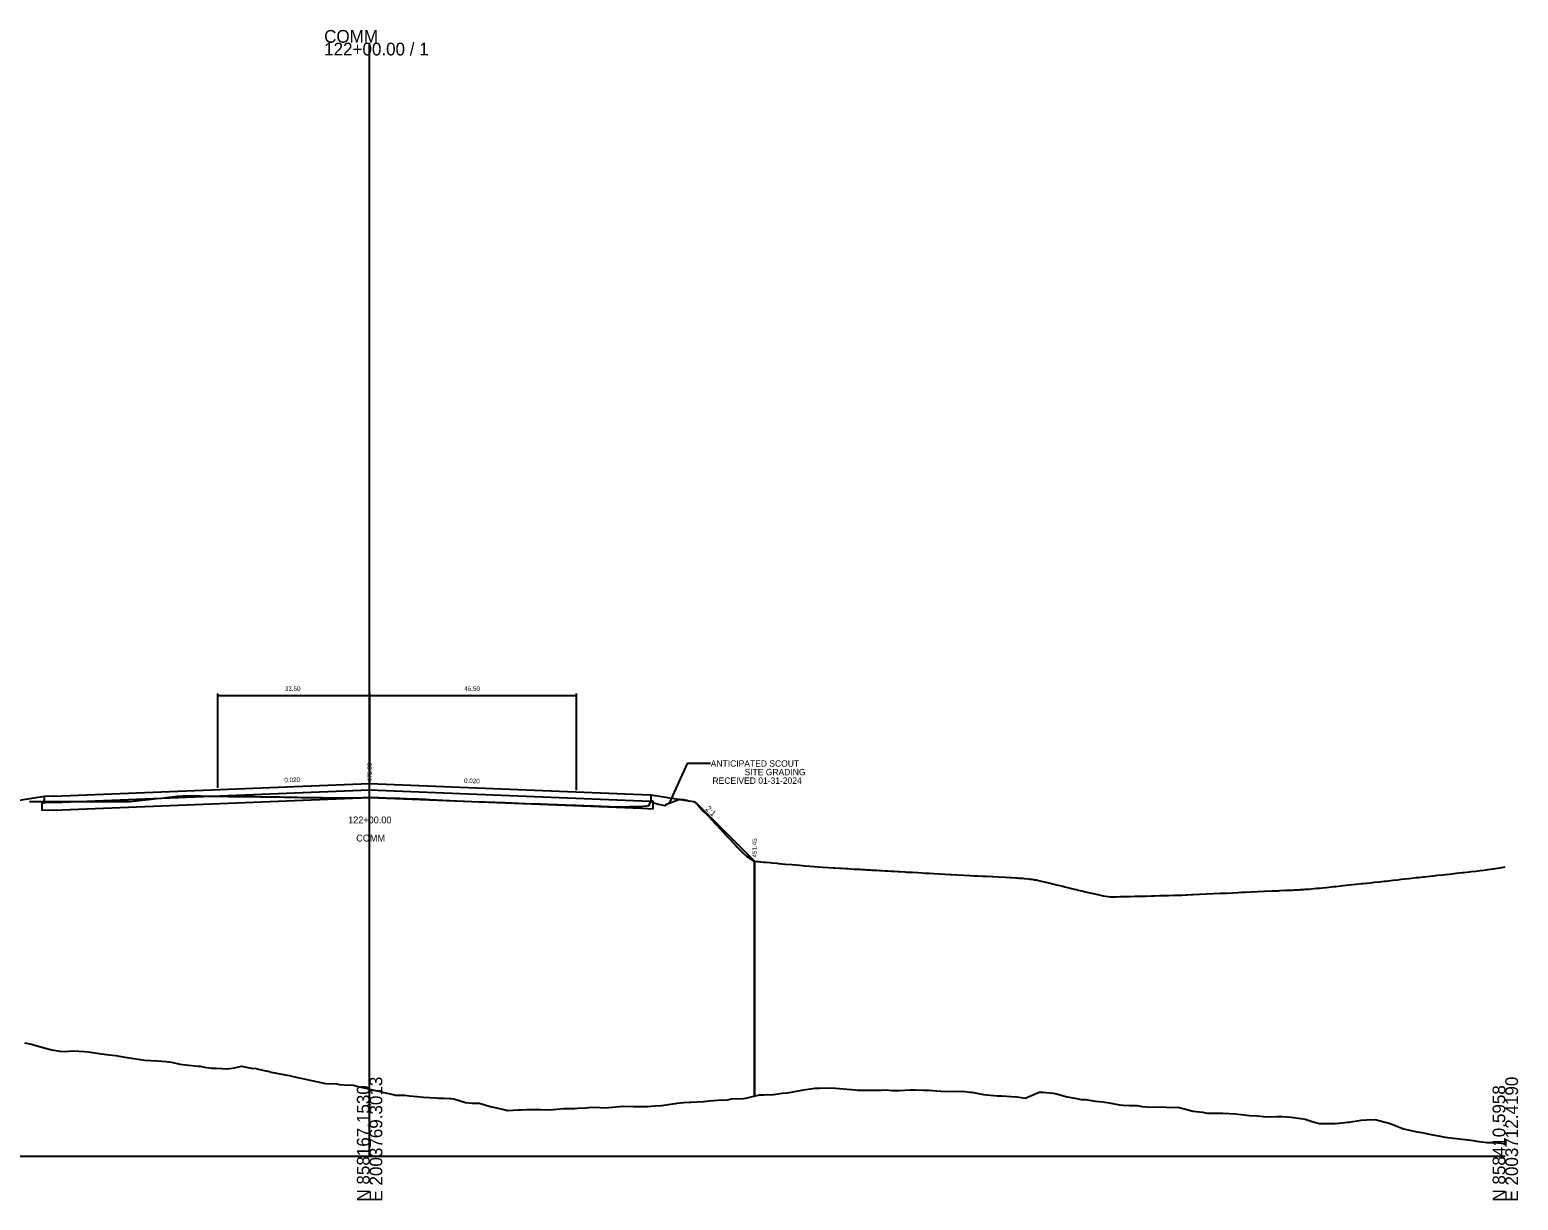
# Model space of a CAD drawing. Extents: x 2058594 to 2062449, y 841632 to 858028.
# Drawn here: x 2061121.7 to 2061449.4, y 856203.8 to 856461.4 of the extents above; entities that cross this region are included whole.
import ezdxf

# ---------------------------------------------------------------- set-up
doc = ezdxf.new("R2010")
doc.units = 0
for name, color, linetype in [('RD_DDB_Profile_Elev', 7, 'Continuous'), ('RD_GPK_XS_Cell', 7, 'Continuous'), ('RD_XS_Base', 7, 'Continuous'), ('RD_XS_EarthShd', 7, 'Continuous'), ('RD_XS_EwShp1', 7, 'Continuous'), ('RD_XS_ExGround', 7, 'Continuous'), ('RD_XS_MatchLine', 7, 'Continuous'), ('RD_XS_Pave', 7, 'Continuous'), ('RD_XS_PaveShd', 7, 'Continuous'), ('RD_XS_TieSlope', 7, 'Continuous'), ('RD_XS_TX_Ditch', 7, 'Continuous'), ('RD_XS_TX_Elev_EX', 7, 'Continuous'), ('RD_XS_TX_Elev_PR', 7, 'Continuous'), ('RD_XS_TX_Misc', 7, 'Continuous'), ('RD_XS_TX_Slope', 7, 'Continuous'), ('RD_XS_TX_Station', 7, 'Continuous')]:
    doc.layers.add(name, color=color, linetype=linetype)

msp = doc.modelspace()

# ---------------------------------------------------------------- linework, layer by layer
at = {"layer": 'RD_DDB_Profile_Elev'}
for points in [[(2061271.56, 856299.94), (2061266.44, 856299.94), (2061262.42, 856291.2)], [(2061121.63, 856291.53), (2061122.12, 856291.53), (2061123.87, 856291.53), (2061124.63, 856291.53), (2061125.19, 856291.53), (2061126.65, 856291.53), (2061129.08, 856291.53), (2061130.16, 856291.53), (2061135.86, 856291.53), (2061137.06, 856291.53), (2061138.02, 856291.53), (2061140.8, 856291.53), (2061141.71, 856291.53), (2061143.71, 856291.53), (2061145.15, 856291.69), (2061147.86, 856292), (2061149.59, 856292.2), (2061150.67, 856292.32), (2061151.27, 856292.39), (2061151.84, 856292.46), (2061152.48, 856292.53), (2061153.12, 856292.61), (2061153.7, 856292.68), (2061154.18, 856292.74), (2061155.51, 856292.84), (2061155.87, 856292.84), (2061156.34, 856292.83), (2061156.89, 856292.82), (2061157.49, 856292.81), (2061158.11, 856292.8), (2061158.72, 856292.79), (2061159.27, 856292.78), (2061159.78, 856292.77), (2061160.11, 856292.77), (2061160.48, 856292.76), (2061160.95, 856292.76), (2061161.57, 856292.75), (2061162.29, 856292.74), (2061163.08, 856292.73), (2061163.52, 856292.73), (2061164.17, 856292.72), (2061164.82, 856292.71), (2061165.47, 856292.7), (2061166.27, 856292.69), (2061166.9, 856292.68), (2061167.8, 856292.67), (2061168.38, 856292.66), (2061169.32, 856292.66), (2061169.82, 856292.65), (2061170.75, 856292.64), (2061171.13, 856292.63), (2061171.54, 856292.63), (2061172.41, 856292.62), (2061172.99, 856292.61), (2061173.77, 856292.6), (2061174.48, 856292.59), (2061175.12, 856292.58), (2061175.94, 856292.57), (2061176.39, 856292.56), (2061176.82, 856292.56), (2061177.71, 856292.54), (2061178.27, 856292.53), (2061179.19, 856292.52), (2061179.86, 856292.51), (2061180.59, 856292.5), (2061181.48, 856292.48), (2061182.25, 856292.47), (2061183.07, 856292.46), (2061183.82, 856292.45), (2061184.52, 856292.43), (2061185.02, 856292.42), (2061186.01, 856292.41), (2061186.31, 856292.4), (2061186.97, 856292.4), (2061187.38, 856292.39), (2061187.83, 856292.38), (2061188.41, 856292.37), (2061188.84, 856292.37), (2061189.16, 856292.36), (2061189.79, 856292.36), (2061190.14, 856292.35), (2061190.51, 856292.35), (2061191.14, 856292.35), (2061192.02, 856292.35), (2061192.89, 856292.36), (2061193.26, 856292.37), (2061194.01, 856292.37), (2061194.51, 856292.39), (2061195.04, 856292.41), (2061195.5, 856292.43), (2061197.59, 856292.45), (2061197.97, 856292.43), (2061198.55, 856292.41), (2061199.32, 856292.37), (2061200.08, 856292.37), (2061200.97, 856292.33), (2061201.65, 856292.33), (2061202.63, 856292.28), (2061203.19, 856292.28), (2061204.23, 856292.23), (2061204.65, 856292.23), (2061206.06, 856292.18), (2061207.22, 856292.13), (2061208.16, 856292.08), (2061208.9, 856292.05), (2061209.74, 856292.01), (2061211.18, 856291.95), (2061212.58, 856291.88), (2061214.12, 856291.81), (2061215.74, 856291.74), (2061217.39, 856291.67), (2061219.01, 856291.59), (2061220.56, 856291.52), (2061222.01, 856291.47), (2061223.25, 856291.42), (2061224.1, 856291.39), (2061225.05, 856291.35), (2061226.28, 856291.31), (2061227.72, 856291.25), (2061229.27, 856291.2), (2061231, 856291.13), (2061232.54, 856291.08), (2061233.79, 856291.03), (2061234.1, 856291.02), (2061234.51, 856291), (2061235.64, 856290.96), (2061236.6, 856290.93), (2061237.13, 856290.91), (2061237.9, 856290.88), (2061238.51, 856290.85), (2061239.06, 856290.83), (2061239.65, 856290.81), (2061240.33, 856290.78), (2061241.12, 856290.76), (2061242.01, 856290.73), (2061242.72, 856290.7), (2061243.65, 856290.66), (2061244.34, 856290.63), (2061245.23, 856290.6), (2061245.85, 856290.58), (2061246.34, 856290.56), (2061247.42, 856290.52), (2061247.74, 856290.5), (2061248.42, 856290.48), (2061248.87, 856290.46), (2061249.4, 856290.44), (2061249.92, 856290.42), (2061251.22, 856290.4), (2061251.56, 856290.41), (2061252.06, 856290.42), (2061252.55, 856290.4), (2061253.14, 856290.41), (2061253.78, 856290.43), (2061254.42, 856290.44), (2061254.99, 856290.46), (2061255.89, 856290.48), (2061256.22, 856290.49), (2061258.04, 856290.71), (2061258.35, 856291.53), (2061258.68, 856291.46), (2061259.09, 856291.3), (2061259.58, 856291.12), (2061260.02, 856290.96), (2061261.48, 856290.66), (2061262.1, 856291.02), (2061262.42, 856291.2), (2061264.77, 856292.08), (2061265.51, 856292.01), (2061265.87, 856291.94), (2061266.32, 856291.85), (2061266.82, 856291.74), (2061267.31, 856291.64), (2061267.88, 856291.53), (2061268.67, 856290.92), (2061269.83, 856289.53), (2061270.94, 856288.45), (2061271.88, 856287.53), (2061273.67, 856285.53), (2061275.16, 856283.95), (2061275.56, 856283.53), (2061276.93, 856282.07), (2061277.43, 856281.53), (2061278.8, 856280.14), (2061279.46, 856279.53), (2061281.15, 856278.44), (2061281.74, 856278.37), (2061282.17, 856278.33), (2061282.58, 856278.29), (2061283.24, 856278.23), (2061283.7, 856278.19), (2061284.6, 856278.11), (2061285.03, 856278.07), (2061286.14, 856277.97), (2061286.49, 856277.94), (2061288.01, 856277.81), (2061289.52, 856277.67), (2061291.18, 856277.53), (2061292.34, 856277.43), (2061293.49, 856277.33), (2061294.33, 856277.26), (2061295.18, 856277.2), (2061296.27, 856277.13), (2061297.54, 856277.05), (2061298.57, 856276.99), (2061298.93, 856276.96), (2061299.94, 856276.9), (2061300.37, 856276.88), (2061301.32, 856276.82), (2061301.81, 856276.79), (2061302.32, 856276.76), (2061303.18, 856276.71), (2061303.69, 856276.68), (2061304.42, 856276.64), (2061304.9, 856276.61), (2061305.48, 856276.57), (2061305.88, 856276.55), (2061306.3, 856276.52), (2061306.69, 856276.5), (2061307.06, 856276.48), (2061307.59, 856276.45), (2061308.06, 856276.42), (2061308.72, 856276.39), (2061309.24, 856276.36), (2061310.02, 856276.31), (2061310.55, 856276.28), (2061311.43, 856276.23), (2061311.94, 856276.2), (2061312.89, 856276.15), (2061313.34, 856276.13), (2061314.33, 856276.07), (2061314.71, 856276.05), (2061315.69, 856275.99), (2061316, 856275.98), (2061317.16, 856275.91), (2061318.13, 856275.86), (2061318.76, 856275.82), (2061319.68, 856275.77), (2061320.71, 856275.72), (2061321.91, 856275.65), (2061323.21, 856275.58), (2061324.26, 856275.53), (2061324.58, 856275.51), (2061326, 856275.43), (2061327.37, 856275.36), (2061328.65, 856275.29), (2061329.58, 856275.24), (2061330.51, 856275.19), (2061331.4, 856275.14), (2061332.22, 856275.1), (2061333.65, 856275.03), (2061334.98, 856274.96), (2061336.52, 856274.89), (2061337.5, 856274.84), (2061337.83, 856274.82), (2061338.73, 856274.77), (2061339.09, 856274.75), (2061339.45, 856274.72), (2061340.25, 856274.67), (2061340.59, 856274.64), (2061341.54, 856274.56), (2061341.84, 856274.51), (2061342.34, 856274.47), (2061342.9, 856274.35), (2061343.22, 856274.31), (2061344.37, 856274.06), (2061346.01, 856273.67), (2061346.59, 856273.53), (2061347.72, 856273.26), (2061349.08, 856272.93), (2061349.52, 856272.82), (2061350.47, 856272.59), (2061351.02, 856272.45), (2061351.58, 856272.31), (2061352.14, 856272.17), (2061352.52, 856272.08), (2061353.29, 856271.9), (2061354.11, 856271.71), (2061355.05, 856271.5), (2061356.14, 856271.25), (2061357.14, 856271.02), (2061358.02, 856270.82), (2061359.62, 856270.6), (2061360, 856270.6), (2061360.45, 856270.61), (2061361, 856270.62), (2061361.68, 856270.64), (2061362.34, 856270.65), (2061363.21, 856270.67), (2061363.93, 856270.69), (2061364.94, 856270.71), (2061365.67, 856270.73), (2061366.79, 856270.76), (2061367.48, 856270.77), (2061368.64, 856270.8), (2061369.26, 856270.82), (2061370.41, 856270.85), (2061370.93, 856270.86), (2061371.99, 856270.89), (2061372.4, 856270.9), (2061373.56, 856270.93), (2061374.44, 856270.96), (2061375.33, 856270.99), (2061376.15, 856271.03), (2061376.46, 856271.04), (2061377.47, 856271.08), (2061377.78, 856271.1), (2061379.22, 856271.16), (2061380.74, 856271.23), (2061382.28, 856271.3), (2061383.8, 856271.36), (2061385.23, 856271.43), (2061386.52, 856271.49), (2061387.63, 856271.54), (2061388.47, 856271.58), (2061389.35, 856271.62), (2061390.52, 856271.67), (2061391.94, 856271.73), (2061393.52, 856271.8), (2061395.21, 856271.88), (2061396.56, 856271.94), (2061396.91, 856271.96), (2061398.18, 856272.02), (2061398.57, 856272.04), (2061399.7, 856272.09), (2061400.1, 856272.11), (2061401.06, 856272.16), (2061401.43, 856272.19), (2061402.19, 856272.23), (2061402.49, 856272.25), (2061403.03, 856272.29), (2061403.35, 856272.31), (2061403.86, 856272.36), (2061404.33, 856272.4), (2061404.95, 856272.46), (2061405.59, 856272.52), (2061406.25, 856272.59), (2061407.05, 856272.67), (2061407.68, 856272.73), (2061408.66, 856272.83), (2061409.19, 856272.89), (2061410.32, 856273.01), (2061410.73, 856273.05), (2061412.22, 856273.21), (2061413.62, 856273.36), (2061414.87, 856273.49), (2061415.23, 856273.53), (2061415.99, 856273.61), (2061416.79, 856273.69), (2061417.66, 856273.79), (2061418.84, 856273.92), (2061419.86, 856274.03), (2061420.26, 856274.07), (2061421.29, 856274.19), (2061421.86, 856274.25), (2061422.82, 856274.36), (2061423.55, 856274.44), (2061424.39, 856274.53), (2061425.27, 856274.63), (2061425.95, 856274.71), (2061426.92, 856274.81), (2061427.43, 856274.87), (2061428.41, 856274.98), (2061428.76, 856275.02), (2061429.89, 856275.15), (2061430.74, 856275.24), (2061431.58, 856275.34), (2061432.72, 856275.46), (2061433.33, 856275.53), (2061434.12, 856275.61), (2061435.72, 856275.79), (2061437.08, 856275.93), (2061437.38, 856275.97), (2061438.6, 856276.1), (2061439.01, 856276.15), (2061440.05, 856276.27), (2061440.51, 856276.32), (2061440.96, 856276.37), (2061441.81, 856276.47), (2061442.2, 856276.52), (2061442.64, 856276.59), (2061443.27, 856276.67), (2061443.94, 856276.77), (2061444.36, 856276.83), (2061445.73, 856277.05), (2061446.51, 856277.18)]]:
    msp.add_lwpolyline(points, dxfattribs=at)
at = {"layer": 'RD_GPK_XS_Cell'}
for p, q in [((2061196.51, 856213.53), (2061196.51, 856458.52)), ((2060946.51, 856213.53), (2061196.51, 856213.53)), ((2061196.51, 856213.53), (2061446.51, 856213.53))]:
    msp.add_line(p, q, dxfattribs=at)
at = {"layer": 'RD_XS_Base'}
for p, q in [((2061126.96, 856289.69), (2061196.51, 856292.48)), ((2061196.51, 856292.48), (2061256.46, 856290.08)), ((2061124.46, 856291.24), (2061124.96, 856291.28)), ((2061124.46, 856289.57), (2061124.46, 856291.24)), ((2061126.96, 856289.69), (2061124.46, 856289.57)), ((2061256.46, 856290.08), (2061258.96, 856289.96)), ((2061258.96, 856291.62), (2061258.46, 856291.66)), ((2061258.96, 856289.96), (2061258.96, 856291.62))]:
    msp.add_line(p, q, dxfattribs=at)
at = {"layer": 'RD_XS_EarthShd'}
for p, q in [((2061124.96, 856292.65), (2061118.96, 856291.69)), ((2061258.46, 856293.03), (2061264.46, 856292.07))]:
    msp.add_line(p, q, dxfattribs=at)
at = {"layer": 'RD_XS_EwShp1'}
for p, q in [((2061124.96, 856292.65), (2061118.96, 856291.69)), ((2061124.96, 856291.28), (2061124.96, 856292.65)), ((2061126.96, 856289.69), (2061196.51, 856292.48)), ((2061196.51, 856292.48), (2061256.46, 856290.08)), ((2061258.46, 856291.66), (2061258.46, 856293.03)), ((2061258.46, 856293.03), (2061264.46, 856292.07)), ((2061264.46, 856292.07), (2061268.21, 856291.47)), ((2061124.46, 856291.24), (2061124.96, 856291.28)), ((2061124.46, 856289.57), (2061124.46, 856291.24)), ((2061126.96, 856289.69), (2061124.46, 856289.57)), ((2061256.46, 856290.08), (2061258.96, 856289.96)), ((2061258.96, 856291.62), (2061258.46, 856291.66)), ((2061258.96, 856289.96), (2061258.96, 856291.62)), ((2061268.21, 856291.47), (2061281.25, 856278.43)), ((2061281.25, 856278.43), (2061281.25, 856226.75))]:
    msp.add_line(p, q, dxfattribs=at)
at = {"layer": 'RD_XS_ExGround'}
msp.add_lwpolyline([(2061120.55, 856238.47), (2061122.07, 856238.19), (2061122.54, 856238.05), (2061125.16, 856237.26), (2061126.56, 856236.91), (2061128.24, 856236.64), (2061129.28, 856236.59), (2061131.32, 856236.67), (2061133.74, 856236.54), (2061134.6, 856236.47), (2061137.48, 856236.08), (2061138.62, 856235.92), (2061140.56, 856235.67), (2061142.64, 856235.29), (2061143.64, 856235.15), (2061146.93, 856234.63), (2061149.81, 856234.52), (2061151.76, 856234.33), (2061152.89, 856234.22), (2061154.71, 856233.8), (2061155.97, 856233.62), (2061158.73, 856233.35), (2061159.25, 856233.3), (2061160.11, 856233.14), (2061161.75, 856232.92), (2061162.13, 856232.88), (2061162.75, 856232.86), (2061165.21, 856232.73), (2061166.75, 856232.96), (2061168.3, 856233.31), (2061170.79, 856232.85), (2061171.38, 856232.88), (2061171.74, 856232.73), (2061173.3, 856232.37), (2061174.46, 856232.13), (2061174.81, 856232.02), (2061177.54, 856231.52), (2061178.83, 856231.26), (2061180.62, 856230.85), (2061181.73, 856230.62), (2061183.7, 856230.19), (2061186.78, 856229.51), (2061189.23, 856229.43), (2061189.86, 856229.29), (2061190.89, 856229.23), (2061192.95, 856229.18), (2061194.22, 856228.76), (2061196.03, 856228.4), (2061196.51, 856228.28), (2061199.11, 856227.67), (2061199.68, 856227.54), (2061201.71, 856227.07), (2061202.19, 856226.98), (2061204.21, 856226.93), (2061205.27, 856226.79), (2061206.98, 856226.64), (2061208.35, 856226.5), (2061211, 856226.34), (2061211.71, 856226.29), (2061212.86, 856226.28), (2061214.2, 856226.24), (2061214.52, 856226.2), (2061215.02, 856226.16), (2061217.6, 856225.37), (2061219.04, 856225.18), (2061220.68, 856225.19), (2061223.06, 856224.45), (2061223.76, 856224.3), (2061226.05, 856223.77), (2061226.84, 856223.61), (2061229.19, 856223.75), (2061229.92, 856223.73), (2061231.1, 856223.78), (2061233, 856223.78), (2061234.19, 856223.79), (2061236.09, 856223.73), (2061239.24, 856224.05), (2061241.68, 856224.05), (2061242.25, 856224.06), (2061244.18, 856224.15), (2061245.33, 856224.29), (2061247.19, 856224.23), (2061248.41, 856224.14), (2061249.17, 856224.24), (2061251.49, 856224.49), (2061252.43, 856224.5), (2061254.57, 856224.46), (2061256.66, 856224.46), (2061257.65, 856224.47), (2061259.25, 856224.62), (2061260.74, 856224.65), (2061263.27, 856225.06), (2061263.82, 856225.11), (2061264.16, 856225.19), (2061265.61, 856225.31), (2061266.9, 856225.41), (2061267.29, 856225.4), (2061269.98, 856225.57), (2061271.31, 856225.73), (2061273.06, 856225.82), (2061275.33, 856225.95), (2061276.14, 856226.11), (2061278.8, 856226.18), (2061279.35, 856226.26), (2061282.31, 856227.02), (2061283.37, 856226.99), (2061285.39, 856227.09), (2061287.4, 856227.37), (2061288.47, 856227.48), (2061291.63, 856228.04), (2061291.99, 856228.1), (2061294.63, 856228.46), (2061295.44, 856228.47), (2061297.71, 856228.57), (2061299.13, 856228.46), (2061300.79, 856228.37), (2061303.48, 856228.09), (2061303.88, 856228.05), (2061305.18, 856228.05), (2061306.96, 856228.03), (2061309.12, 856228.06), (2061310.04, 856228.09), (2061311.52, 856227.98), (2061313.12, 856227.99), (2061315.54, 856228.12), (2061316.2, 856228.13), (2061316.61, 856228.11), (2061318.36, 856228.07), (2061319.56, 856228.04), (2061322.36, 856227.81), (2061323.58, 856227.73), (2061325.45, 856227.81), (2061327.6, 856227.73), (2061328.53, 856227.63), (2061329.1, 856227.6), (2061331.62, 856227.12), (2061334.69, 856226.82), (2061335.65, 856226.77), (2061337.77, 856226.64), (2061339.09, 856226.55), (2061340.85, 856226.31), (2061343.93, 856227.63), (2061344.74, 856227.59), (2061347.01, 856227.37), (2061347.71, 856227.21), (2061350.1, 856226.58), (2061351.73, 856226.32), (2061353.18, 856225.98), (2061354.08, 856225.96), (2061356.26, 856225.66), (2061357.93, 856225.46), (2061359.34, 856225.25), (2061361.57, 856224.82), (2061362.42, 856224.75), (2061363.79, 856224.68), (2061365.5, 856224.64), (2061366.57, 856224.47), (2061368.58, 856224.32), (2061371.11, 856224.35), (2061371.83, 856224.34), (2061374.75, 856224.21), (2061375.85, 856223.91), (2061377.83, 856223.44), (2061379.88, 856223.18), (2061380.91, 856223.02), (2061383.99, 856223.01), (2061384.3, 856223), (2061387.07, 856222.86), (2061389.05, 856222.63), (2061390.15, 856222.5), (2061391.94, 856222.4), (2061393.24, 856222.28), (2061394.04, 856222.21), (2061396.32, 856222.25), (2061397.49, 856222.22), (2061399.4, 856222.13), (2061401.53, 856221.79), (2061402.48, 856221.7), (2061404, 856221.17), (2061405.56, 856220.7), (2061406.53, 856220.68), (2061408.64, 856220.72), (2061409.03, 856220.73), (2061410.68, 856220.89), (2061411.72, 856221), (2061412.04, 856221.03), (2061414.8, 856221.43), (2061416.06, 856221.53), (2061417.89, 856221.63), (2061420.08, 856221.02), (2061420.97, 856220.77), (2061421.52, 856220.57), (2061424.1, 856219.55), (2061427.13, 856218.88), (2061428.13, 856218.72), (2061430.21, 856218.33), (2061432.15, 856217.96), (2061433.29, 856217.72), (2061436.37, 856217.31), (2061437.05, 856217.25), (2061439, 856217.06), (2061439.46, 856216.96), (2061440.19, 856216.85), (2061442.54, 856216.5), (2061444, 856216.5), (2061445.62, 856216.4), (2061446.51, 856216.26)], dxfattribs=at)
at = {"layer": 'RD_XS_MatchLine'}
msp.add_line((2061281.25, 856226.75), (2061281.25, 856278.43), dxfattribs=at)
at = {"layer": 'RD_XS_Pave'}
for p, q in [((2061126.96, 856292.73), (2061196.51, 856295.51)), ((2061196.51, 856295.51), (2061256.46, 856293.11)), ((2061126.96, 856291.36), (2061196.51, 856294.14)), ((2061196.51, 856294.14), (2061256.46, 856291.74))]:
    msp.add_line(p, q, dxfattribs=at)
at = {"layer": 'RD_XS_PaveShd'}
for p, q in [((2061126.96, 856292.73), (2061124.96, 856292.65)), ((2061124.96, 856291.28), (2061124.96, 856292.65)), ((2061256.46, 856293.11), (2061258.46, 856293.03)), ((2061256.46, 856291.74), (2061258.46, 856291.66)), ((2061258.46, 856291.66), (2061258.46, 856293.03)), ((2061126.96, 856291.36), (2061124.96, 856291.28))]:
    msp.add_line(p, q, dxfattribs=at)
at = {"layer": 'RD_XS_TieSlope'}
for p, q in [((2061264.46, 856292.07), (2061268.21, 856291.47)), ((2061268.21, 856291.47), (2061281.25, 856278.43))]:
    msp.add_line(p, q, dxfattribs=at)
at = {"layer": 'RD_XS_TX_Misc'}
for p, q in [((2061163.01, 856315.31), (2061163.01, 856294.57)), ((2061163.01, 856314.91), (2061196.51, 856314.91)), ((2061196.51, 856315.31), (2061196.51, 856295.91)), ((2061196.51, 856314.91), (2061242.01, 856314.91)), ((2061242.01, 856315.31), (2061242.01, 856294.09))]:
    msp.add_line(p, q, dxfattribs=at)

# ---------------------------------------------------------------- texts
at = {"layer": 'RD_DDB_Profile_Elev'}
for s, p in [('ANTICIPATED SCOUT', (2061271.61, 856299.22)), ('SITE GRADING', (2061279.05, 856297.34)), ('RECEIVED 01-31-2024', (2061271.98, 856295.45))]:
    msp.add_text(s, height=1.4, dxfattribs=at).set_placement(p)
at = {"layer": 'RD_GPK_XS_Cell'}
for s, p in [('COMM', (2061186.51, 856458.52)), ('122+00.00 / 1', (2061186.51, 856455.72))]:
    msp.add_text(s, height=2.8, dxfattribs=at).set_placement(p)
for s, p in [('E 2003769.3013', (2061199.31, 856203.53)), ('E 2003712.4190', (2061449.31, 856203.53)), ('N 858167.1530', (2061196.51, 856203.53)), ('N 858410.5958', (2061446.51, 856203.53))]:
    msp.add_text(s, height=2.8, rotation=90, dxfattribs=at).set_placement(p)
at = {"layer": 'RD_XS_TX_Ditch'}
msp.add_text('451.45', height=1, rotation=90, dxfattribs=at).set_placement((2061281.75, 856279.23))
at = {"layer": 'RD_XS_TX_Elev_EX'}
msp.add_text('442.38', height=0.8, rotation=270, dxfattribs=at).set_placement((2061196.11, 856226.28))
at = {"layer": 'RD_XS_TX_Elev_PR'}
msp.add_text(' 475.99', height=1, rotation=90, dxfattribs=at).set_placement((2061197.01, 856295.51))
at = {"layer": 'RD_XS_TX_Misc'}
for s, p in [('33.50', (2061177.85, 856315.91)), ('45.50', (2061217.35, 856315.91))]:
    msp.add_text(s, height=1, dxfattribs=at).set_placement(p)
at = {"layer": 'RD_XS_TX_Slope'}
for s, height, rotation, p in [('0.020', 1, 2.2906, (2061177.76, 856295.76)), ('0.020', 1, 357.7094, (2061217.28, 856295.68)), ('2:1', 1.25, 315, (2061270.39, 856289.86))]:
    msp.add_text(s, height=height, rotation=rotation, dxfattribs=at).set_placement(p)
at = {"layer": 'RD_XS_TX_Station'}
for s, p in [('122+00.00', (2061191.79, 856286.76)), ('COMM', (2061193.57, 856282.76))]:
    msp.add_text(s, height=1.5, dxfattribs=at).set_placement(p)

doc.saveas('drawing.dxf')
